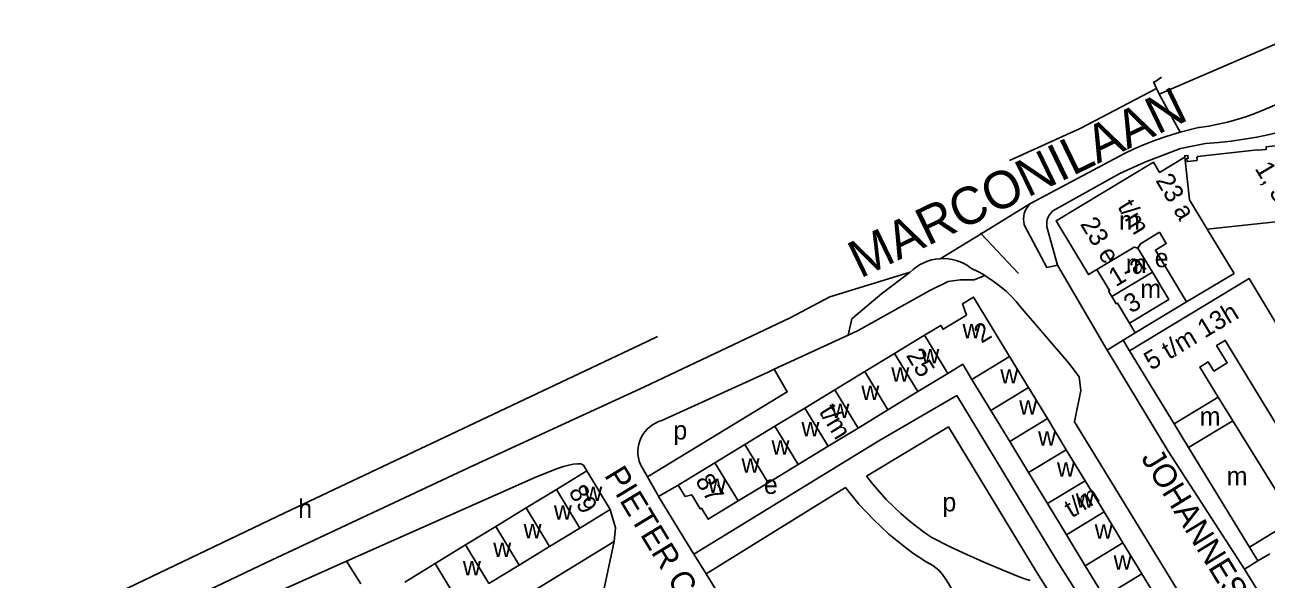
# Model space of a CAD drawing. Extents: x 159902 to 161769, y 383692 to 384875.
# Drawn here: x 160063.3 to 160329.3, y 384623.4 to 384742.2 of the extents above; entities that cross this region are included whole.
import ezdxf

# ---------------------------------------------------------------- set-up
doc = ezdxf.new("R2010")
doc.units = 0
for name, color, linetype in [('BLT_Basislijn', 7, 'Continuous'), ('BLT_Bebouwing', 7, 'Continuous'), ('BLT_Centroide', 7, 'Continuous'), ('BLT_Huisnummer', 7, 'Continuous'), ('BLT_Huisnummer_reeks', 7, 'Continuous'), ('BLT_Onderdoorgang_en_onderverdeling', 7, 'Continuous'), ('BLT_Onderverdeling_panden', 7, 'Continuous'), ('BLT_Straatnaam', 7, 'Continuous'), ('BLT_Straatnaam_hoofdweg', 7, 'Continuous'), ('BLT_Vlakafsluiter', 7, 'Continuous')]:
    doc.layers.add(name, color=color, linetype=linetype)

msp = doc.modelspace()

# ---------------------------------------------------------------- linework, layer by layer
at = {"layer": 'BLT_Basislijn'}
for p, q in [((160305.86, 384728.55), (160305.29, 384729.87)), ((160278.66, 384703.83), (160299, 384714.67)), ((160268.11, 384697.61), (160268.25, 384697.46)), ((160268.25, 384697.46), (160276.26, 384688.94)), ((160282.49, 384698.4), (160284.58, 384690.7)), ((160284.58, 384690.7), (160295.26, 384672.51)), ((160312.29, 384682.83), (160301.28, 384676.22)), ((160276.61, 384681.83), (160287.02, 384669.69)), ((160300.02, 384678.3), (160301.28, 384676.22)), ((160223.89, 384668.39), (160239.76, 384675.7)), ((160298.66, 384674.61), (160295.26, 384672.51)), ((160301.28, 384676.22), (160298.66, 384674.61)), ((160300.07, 384672.31), (160298.66, 384674.61)), ((160308.36, 384650.83), (160295.26, 384672.51)), ((160199.83, 384657.39), (160222.58, 384667.79)), ((160222.58, 384667.79), (160223.89, 384668.39)), ((160243.64, 384645.47), (160261.23, 384656.07)), ((160308.36, 384650.83), (160324.68, 384625.57)), ((160132.18, 384627.22), (160172.94, 384645.36)), ((160172.94, 384645.36), (160177.41, 384647.13)), ((160196.73, 384645.3), (160195.3, 384647.85)), ((160199.12, 384641.1), (160203.29, 384643.55)), ((160239.2, 384643.05), (160209.3, 384624.57)), ((160199.12, 384641.1), (160206.69, 384628.75)), ((160107.62, 384581.31), (160189.56, 384631.47)), ((160325.76, 384630.24), (160327.55, 384627.3)), ((160091.91, 384609.29), (160132.18, 384627.22)), ((160135.26, 384622.36), (160132.18, 384627.22)), ((160206.69, 384628.75), (160209.3, 384624.57)), ((160327.55, 384627.3), (160324.68, 384625.57)), ((160330.12, 384628.85), (160327.55, 384627.3)), ((160230.83, 384589.77), (160209.3, 384624.57)), ((160276.42, 384623.92), (160277.63, 384623.46)), ((160278.74, 384623.13), (160277.63, 384623.46))]:
    msp.add_line(p, q, dxfattribs=at)
for points in [[(160340.9, 384742.23), (160306.38, 384727.35)], [(160305.29, 384729.87), (160306.89, 384731.02)], [(160305.86, 384728.55), (160289.44, 384720.03), (160274.33, 384713.17)], [(160306.38, 384727.35), (160305.86, 384728.55)], [(160314.98, 384720.23), (160317.02, 384720.54), (160319.04, 384720.92), (160321.05, 384721.38), (160323.04, 384721.91), (160325, 384722.53), (160326.94, 384723.22), (160328.85, 384723.98), (160330.73, 384724.82), (160331.31, 384725.1)], [(160316.37, 384716.76), (160319.12, 384716.99), (160321.86, 384717.31), (160324.6, 384717.71), (160327.31, 384718.18), (160330.02, 384718.73), (160332.7, 384719.36), (160335.37, 384720.07), (160338.02, 384720.86), (160340.64, 384721.72), (160343.23, 384722.66), (160345.03, 384723.36)], [(160310.93, 384719.24), (160314.8, 384720.19), (160314.98, 384720.23)], [(160299, 384714.67), (160301.17, 384715.69), (160303.38, 384716.63), (160305.61, 384717.49), (160307.88, 384718.28), (160310.93, 384719.24)], [(160284.24, 384702.69), (160297.96, 384710.33), (160303.34, 384712.76), (160310.99, 384715.72), (160316.37, 384716.76)], [(160278.66, 384703.83), (160278.3, 384703.33), (160277.96, 384702.85), (160277.69, 384702.32), (160277.49, 384701.77), (160277.37, 384701.19), (160277.33, 384700.6), (160277.36, 384700.02), (160277.48, 384699.44), (160277.61, 384699.04)], [(160282.49, 384698.4), (160282.36, 384698.92), (160282.3, 384699.44), (160282.33, 384699.97), (160282.43, 384700.49), (160282.61, 384700.99), (160282.86, 384701.46), (160283.18, 384701.88), (160283.56, 384702.25), (160283.99, 384702.55), (160284.24, 384702.69)], [(160277.61, 384699.04), (160282.33, 384690.18), (160284.58, 384690.7)], [(160253.04, 384689.21), (160253.69, 384689.81), (160254.4, 384690.35), (160255.15, 384690.83), (160255.95, 384691.23), (160256.77, 384691.56), (160257.62, 384691.82), (160258.5, 384692), (160259.47, 384692.1)], [(160259.47, 384692.1), (160260.27, 384692.12), (160261.16, 384692.06), (160262.04, 384691.92), (160262.9, 384691.7), (160263.74, 384691.41), (160264.55, 384691.04), (160265.33, 384690.6), (160266.06, 384690.09), (160266.21, 384689.98)], [(160253.04, 384689.21), (160246.96, 384684.6), (160240.54, 384679.22), (160239.76, 384675.7)], [(160257.27, 384685.29), (160261.18, 384687.2), (160263.78, 384687.55), (160266.73, 384687.55), (160269, 384688.51)], [(160266.21, 384689.98), (160267.55, 384689.32), (160268.86, 384688.6), (160269, 384688.51)], [(160269, 384688.51), (160270.12, 384687.8), (160271.35, 384686.95), (160272.52, 384686.02), (160273.65, 384685.04), (160274.72, 384683.99), (160275.73, 384682.89), (160276.61, 384681.83)], [(160239.76, 384675.7), (160241.91, 384676.69), (160257.27, 384685.29)], [(160159.61, 384647.8), (160196.11, 384664.66), (160227.31, 384679.4), (160235.8, 384683.91)], [(160196.63, 384674.33), (160198.9, 384675.44)], [(160046.76, 384603.09), (160071.81, 384615.04), (160118.96, 384637.58), (160196.63, 384674.33)], [(160289.64, 384663.82), (160289.27, 384666.74), (160287.02, 384669.69)], [(160223.89, 384668.39), (160226.7, 384663.52), (160196.73, 384645.3)], [(160206.69, 384628.75), (160246.34, 384653.03), (160263.01, 384662.77)], [(160289.64, 384663.82), (160288.27, 384657.09), (160314.43, 384614.39), (160315.55, 384613.23), (160316.23, 384613.15), (160319.69, 384615.3), (160320.39, 384615.22), (160323.06, 384611.25), (160322.97, 384609.82), (160322.01, 384605.11), (160319.46, 384603.11), (160243.77, 384557.03), (160242.91, 384556.57), (160241.08, 384556.42), (160238.16, 384560.86)], [(160263.01, 384662.77), (160284.43, 384627.48), (160295.18, 384610.46)], [(160199.83, 384657.39), (160199.12, 384657.17), (160198.44, 384656.86), (160197.8, 384656.49), (160197.2, 384656.06), (160196.65, 384655.56), (160196.16, 384655), (160195.73, 384654.4), (160195.37, 384653.75), (160195.08, 384653.06), (160194.86, 384652.35), (160194.73, 384651.62), (160194.67, 384650.88), (160194.69, 384650.14), (160194.79, 384649.41), (160194.97, 384648.69), (160195.23, 384647.99), (160195.3, 384647.85)], [(160261.23, 384656.07), (160280.18, 384624.85), (160288.2, 384612.14)], [(160183.72, 384646.61), (160183, 384647.82), (160182.47, 384648.09), (160181.69, 384648.15), (160180.81, 384648.01), (160179.86, 384647.84), (160178.73, 384647.57), (160177.41, 384647.13)], [(160051.44, 384596.66), (160115.06, 384627), (160159.61, 384647.8)], [(160199.12, 384641.1), (160198.77, 384641.68), (160196.73, 384645.3)], [(160243.64, 384645.47), (160245.01, 384643.76), (160246.43, 384642.1), (160247.91, 384640.49), (160249.45, 384638.95), (160251.05, 384637.45), (160252.7, 384636.02), (160254.4, 384634.65), (160256.15, 384633.34), (160257.64, 384632.3)], [(160239.2, 384643.05), (160240.6, 384641.25), (160242.06, 384639.5), (160243.57, 384637.81), (160245.15, 384636.17), (160246.78, 384634.58), (160248.47, 384633.06), (160250.21, 384631.59), (160252, 384630.19), (160253.84, 384628.85), (160254.84, 384628.16)], [(160188.75, 384638.31), (160189.87, 384634.39), (160189.56, 384631.47)], [(160257.64, 384632.3), (160261.46, 384630.43), (160265.31, 384628.63), (160269.2, 384626.9), (160273.12, 384625.25), (160276.42, 384623.92)], [(160128.46, 384578.9), (160186.26, 384615.77), (160189.56, 384631.47)], [(160257.26, 384626.66), (160256.08, 384627.34), (160254.95, 384628.08), (160254.84, 384628.16)], [(160259.18, 384625.32), (160258.54, 384625.85), (160257.86, 384626.32), (160257.26, 384626.66)], [(160259.18, 384625.32), (160259.93, 384624.42), (160260.62, 384623.47), (160261.24, 384622.48), (160261.79, 384621.45), (160262.27, 384620.39), (160262.68, 384619.29), (160263.01, 384618.17), (160263.26, 384617.03), (160263.43, 384615.87), (160263.53, 384614.7), (160263.54, 384613.54), (160263.48, 384612.37), (160263.33, 384611.21), (160263.28, 384610.89)], [(160324.68, 384625.57), (160348.56, 384586.9), (160376.7, 384540.59), (160381.79, 384542.97)]]:
    msp.add_lwpolyline(points, dxfattribs=at)
at = {"layer": 'BLT_Bebouwing'}
for p, q in [((160316.7, 384698.46), (160322.46, 384688.94)), ((160304.95, 384689.2), (160301.86, 384694.35)), ((160256.12, 384675.7), (160249.7, 384671.79)), ((160309.59, 384656.71), (160300.07, 384672.31)), ((160249.7, 384671.79), (160243.28, 384667.89)), ((160278.4, 384664.46), (160274.35, 384671.12)), ((160243.28, 384667.89), (160236.86, 384663.98)), ((160254.68, 384663.6), (160261.1, 384667.5)), ((160236.86, 384663.98), (160230.44, 384660.07)), ((160266.27, 384666.2), (160270.32, 384659.55)), ((160282.45, 384657.81), (160278.4, 384664.46)), ((160248.27, 384659.69), (160254.68, 384663.6)), ((160319.07, 384662.43), (160322.2, 384657.31)), ((160230.44, 384660.07), (160224.02, 384656.17)), ((160241.85, 384655.78), (160248.27, 384659.69)), ((160270.32, 384659.55), (160274.37, 384652.89)), ((160224.02, 384656.17), (160217.6, 384652.26)), ((160286.5, 384651.15), (160282.45, 384657.81)), ((160309.59, 384656.71), (160312.72, 384651.59)), ((160235.43, 384651.88), (160241.85, 384655.78)), ((160217.6, 384652.26), (160211.18, 384648.35)), ((160229, 384647.97), (160235.43, 384651.88)), ((160274.37, 384652.89), (160278.42, 384646.23)), ((160290.55, 384644.49), (160286.5, 384651.15)), ((160325.76, 384630.24), (160312.72, 384651.59)), ((160211.18, 384648.35), (160203.29, 384643.55)), ((160222.58, 384644.06), (160229, 384647.97)), ((160177.22, 384642.64), (160183.72, 384646.61)), ((160183.72, 384646.61), (160188.75, 384638.31)), ((160278.42, 384646.23), (160282.47, 384639.58)), ((160177.22, 384642.64), (160170.72, 384638.66)), ((160216.16, 384640.16), (160222.58, 384644.06)), ((160294.6, 384637.84), (160290.55, 384644.49)), ((160170.72, 384638.66), (160164.22, 384634.69)), ((160188.75, 384638.31), (160182.25, 384634.34)), ((160282.47, 384639.58), (160286.52, 384632.92)), ((160298.65, 384631.18), (160294.6, 384637.84)), ((160164.22, 384634.69), (160157.73, 384630.72)), ((160182.25, 384634.34), (160175.75, 384630.37)), ((160286.52, 384632.92), (160290.57, 384626.27)), ((160157.73, 384630.72), (160151.23, 384626.75)), ((160175.75, 384630.37), (160169.25, 384626.4)), ((160302.7, 384624.53), (160298.65, 384631.18)), ((160151.23, 384626.75), (160144.73, 384622.78)), ((160169.25, 384626.4), (160162.75, 384622.43)), ((160290.57, 384626.27), (160294.62, 384619.61)), ((160306.76, 384617.87), (160302.7, 384624.53))]:
    msp.add_line(p, q, dxfattribs=at)
for points in [[(160311.92, 384713.85), (160311.88, 384714.15), (160312.57, 384714.24), (160312.65, 384713.63), (160312.31, 384713.59), (160312.39, 384712.93), (160314.53, 384713.17), (160314.46, 384713.84), (160314.66, 384713.86), (160314.65, 384713.99), (160327.45, 384715.43), (160327.46, 384715.33), (160329.37, 384715.53), (160329.31, 384716.07), (160345.4, 384717.89), (160345.91, 384713.55), (160352.91, 384714.34), (160352.1, 384721.17), (160364.98, 384722.61), (160365.28, 384720.31), (160373.03, 384725.04)], [(160311.92, 384713.85), (160306.49, 384710.58), (160305.18, 384712.76), (160284.32, 384700.24), (160291.25, 384688.68), (160293.05, 384689.76)], [(160373.35, 384684.92), (160372.17, 384686.88), (160371.09, 384686.24), (160363.06, 384699.6), (160354.5, 384698.69), (160354.1, 384702.41), (160316.7, 384698.46)], [(160301.86, 384694.35), (160302.38, 384695.3), (160306.47, 384697.76)], [(160306.47, 384697.76), (160307.93, 384695.34), (160305.61, 384693.95), (160312.29, 384682.83)], [(160293.05, 384689.76), (160295.76, 384685.25), (160295.55, 384685.13), (160296.25, 384683.97)], [(160300.02, 384678.3), (160308.45, 384683.38), (160304.95, 384689.2)], [(160300.07, 384672.31), (160325.68, 384687.88), (160340.8, 384662.72), (160366.48, 384678.15), (160376.62, 384661.32), (160341.66, 384639.95), (160320.57, 384674.59), (160318.71, 384673.45), (160320.98, 384669.78), (160318.13, 384668.01), (160316.9, 384670), (160315.09, 384668.87), (160319.07, 384662.43)], [(160312.29, 384682.83), (160322.46, 384688.94)], [(160274.35, 384671.12), (160266.61, 384683.85), (160264.23, 384682.4), (160265.09, 384680.02), (160260.08, 384676.97), (160259.58, 384677.8), (160256.12, 384675.7)], [(160296.25, 384683.97), (160297.18, 384682.43), (160297.44, 384682.58), (160300.02, 384678.3)], [(160261.1, 384667.5), (160264.3, 384669.45), (160266.27, 384666.2)], [(160322.2, 384657.31), (160335.35, 384636.12), (160325.76, 384630.24)], [(160203.29, 384643.55), (160204.77, 384641.12), (160206.21, 384641.49), (160208.05, 384638.46), (160208.3, 384638.62), (160209.74, 384636.25), (160216.16, 384640.16)]]:
    msp.add_lwpolyline(points, dxfattribs=at)
at = {"layer": 'BLT_Onderdoorgang_en_onderverdeling'}
for p, q in [((160309.59, 384656.71), (160319.07, 384662.43)), ((160312.72, 384651.59), (160322.2, 384657.31))]:
    msp.add_line(p, q, dxfattribs=at)
at = {"layer": 'BLT_Onderverdeling_panden'}
for p, q in [((160311.92, 384713.85), (160312.91, 384704.72)), ((160312.91, 384704.72), (160316.7, 384698.46)), ((160296.25, 384683.97), (160304.95, 384689.2)), ((160261.1, 384667.5), (160256.12, 384675.7)), ((160254.68, 384663.6), (160249.7, 384671.79)), ((160266.27, 384666.2), (160274.35, 384671.12)), ((160248.27, 384659.69), (160243.28, 384667.89)), ((160241.85, 384655.78), (160236.86, 384663.98)), ((160270.32, 384659.55), (160278.4, 384664.46)), ((160235.43, 384651.88), (160230.44, 384660.07)), ((160229, 384647.97), (160224.02, 384656.17)), ((160274.37, 384652.89), (160282.45, 384657.81)), ((160222.58, 384644.06), (160217.6, 384652.26)), ((160278.42, 384646.23), (160286.5, 384651.15)), ((160216.16, 384640.16), (160211.18, 384648.35)), ((160177.22, 384642.64), (160182.25, 384634.34)), ((160282.47, 384639.58), (160290.55, 384644.49)), ((160170.72, 384638.66), (160175.75, 384630.37)), ((160286.52, 384632.92), (160294.6, 384637.84)), ((160169.25, 384626.4), (160164.22, 384634.69)), ((160162.75, 384622.43), (160157.73, 384630.72)), ((160290.57, 384626.27), (160298.65, 384631.18)), ((160156.25, 384618.46), (160151.23, 384626.75)), ((160294.62, 384619.61), (160302.7, 384624.53))]:
    msp.add_line(p, q, dxfattribs=at)
msp.add_lwpolyline([(160293.05, 384689.76), (160301.08, 384694.58), (160301.86, 384694.35)], dxfattribs=at)
at = {"layer": 'BLT_Vlakafsluiter'}
for p, q in [((160305.29, 384729.87), (160305.16, 384730.07)), ((160306.38, 384727.35), (160310.93, 384719.24)), ((160268.25, 384697.46), (160278.66, 384703.83)), ((160259.47, 384692.1), (160268.25, 384697.46)), ((160235.8, 384683.91), (160253.04, 384689.21))]:
    msp.add_line(p, q, dxfattribs=at)

# ---------------------------------------------------------------- texts
at = {"layer": 'BLT_Centroide'}
for s, p in [('m', (160297.81, 384698.34)), ('e', (160305.45, 384690.27)), ('m', (160299.25, 384689.06)), ('m', (160302.36, 384683.66)), ('w', (160264.25, 384675.03)), ('w', (160255.41, 384669.64)), ('w', (160248.98, 384665.73)), ('w', (160272.34, 384665.34)), ('w', (160242.56, 384661.83)), ('w', (160276.39, 384658.69)), ('w', (160236.14, 384657.92)), ('m', (160315.09, 384656.3)), ('p', (160202.27, 384653.33)), ('w', (160229.72, 384654.02)), ('w', (160280.44, 384652.03)), ('w', (160223.3, 384650.11)), ('w', (160216.88, 384646.2)), ('w', (160284.49, 384645.38)), ('m', (160320.88, 384643.5)), ('w', (160183.17, 384640.14)), ('w', (160209.72, 384641.88)), ('e', (160221.68, 384641.67)), ('h', (160121.86, 384636.54)), ('p', (160259.94, 384637.92)), ('w', (160288.54, 384638.72)), ('w', (160176.67, 384636.16)), ('w', (160170.16, 384632.17)), ('w', (160292.59, 384632.06)), ('w', (160163.66, 384628.17)), ('w', (160157.16, 384624.2)), ('w', (160296.64, 384625.41))]:
    msp.add_text(s, height=4, dxfattribs=at).set_placement(p)
at = {"layer": 'BLT_Huisnummer'}
msp.add_text('3', height=4, rotation=31.0117, dxfattribs=at).set_placement((160300.35, 384680.27))
at = {"layer": 'BLT_Huisnummer_reeks'}
for s, rotation, p in [('1, 3 01 t/m 23', 301.0133, (160326.81, 384711.44)), ('23 a', 301.0133, (160305.52, 384708.88)), ('t/m', 301.0133, (160297.36, 384703.27)), ('23 e', 301.0133, (160289.37, 384699.54)), ('1-a', 31.0054, (160297.1, 384685.96)), ('5 t/m 13h', 31.0133, (160304.69, 384668.06)), ('2', 31.3222, (160268.3, 384673.83)), ('25', 301.3203, (160252.05, 384671.38)), ('t/m', 301.3223, (160233.36, 384659.33)), ('87', 301.3161, (160206.86, 384644.49)), ('89', 301.4923, (160179.71, 384642.11)), ('t/m', 31.3213, (160287.64, 384636.42))]:
    msp.add_text(s, height=4, rotation=rotation, dxfattribs=at).set_placement(p)
at = {"layer": 'BLT_Straatnaam'}
for s, rotation, p in [('JOHANNES VAN DER WAALSWEG', 301.4898, (160302.4, 384649.36)), ('PIETER CALANDSTRAAT', 301.2851, (160187.34, 384645.67))]:
    msp.add_text(s, height=5, rotation=rotation, dxfattribs=at).set_placement(p)
at = {"layer": 'BLT_Straatnaam_hoofdweg'}
msp.add_text('MARCONILAAN', height=8, rotation=25.8221, dxfattribs=at).set_placement((160242.35, 384687.79))

doc.saveas('drawing.dxf')
